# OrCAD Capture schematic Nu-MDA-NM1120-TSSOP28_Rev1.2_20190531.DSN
size A4; title: NM1120_MDA; rev: V1.2
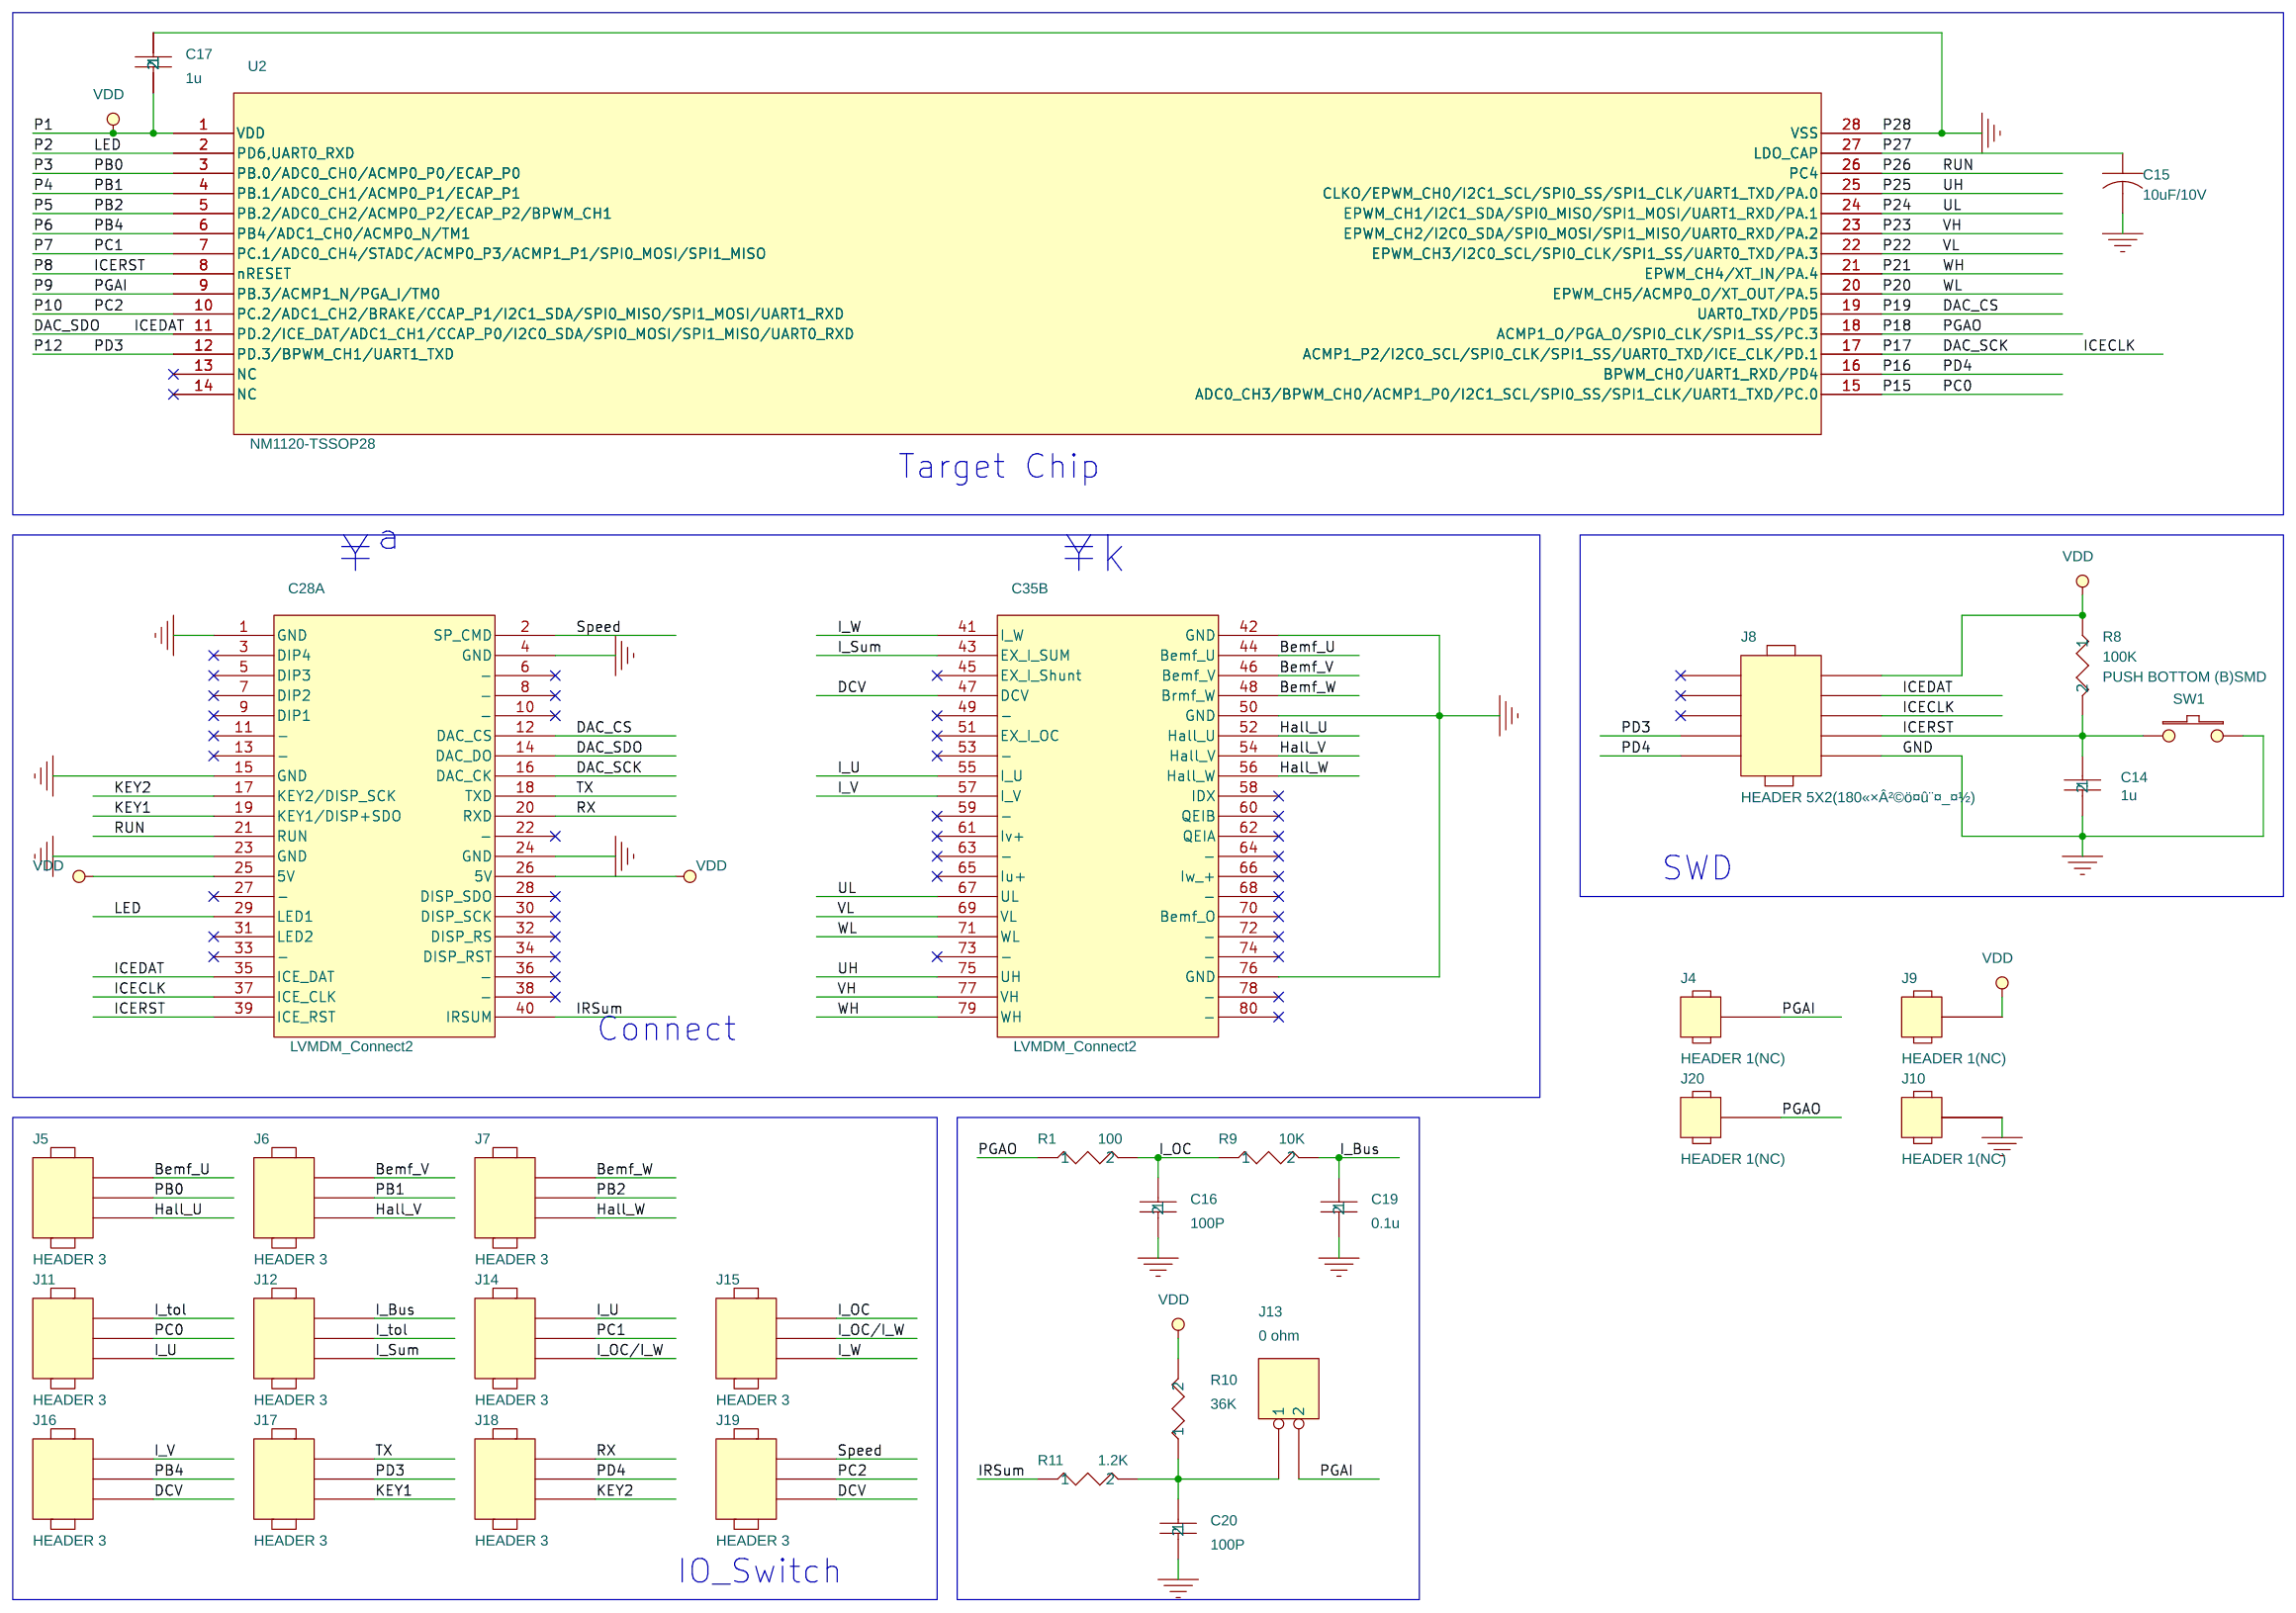
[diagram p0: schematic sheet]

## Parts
C14  1u  [C0603]
C15  10uF/10V  [TANT-A]
C16  100P  [C0603]
C17  1u  [C0603]
C19  0.1u  [C0603]
C20  100P  [C0603]
C28  LVMDM_Connect2  [LVMDM_Connect]  (section A)
C35  LVMDM_Connect2  [LVMDM_Connect]  (section B)
J4  HEADER 1(NC)  [sip-1p]
J5  HEADER 3  [HEADER3]
J6  HEADER 3  [HEADER3]
J7  HEADER 3  [HEADER3]
J8  HEADER 5X2(180«×Â²©ö¤û¨¤_¤½)  [header2x5]
J9  HEADER 1(NC)  [sip-1p]
J10  HEADER 1(NC)  [sip-1p]
J11  HEADER 3  [HEADER3]
J12  HEADER 3  [HEADER3]
J13  0 ohm  [SIP-2P]
J14  HEADER 3  [HEADER3]
J15  HEADER 3  [HEADER3]
J16  HEADER 3  [HEADER3]
J17  HEADER 3  [HEADER3]
J18  HEADER 3  [HEADER3]
J19  HEADER 3  [HEADER3]
J20  HEADER 1(NC)  [sip-1p]
R1  100  [R0603]
R8  100K  [R0603]
R9  10K  [R0603]
R10  36K  [R0603]
R11  1.2K  [R0603]
SW1  PUSH BOTTOM (B)SMD  [SW_SMD_HSM]
U2  NM1120-TSSOP28  [TSSOP28_1]

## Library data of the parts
C14 = C_1u
C15 = C_1uF_16V
C16 = C_0.1u_1
C17 = C_0.1u_3
C19 = C_0.1u
C20 = C_0.1u_2
C28 C35 = LVMDM_Connect2
J4 J9 J10 J20 = HEADER_1
J5-J7 J11 J12 J14-J19 = HEADER_3
J8 = HEADER_5X2
J13 = Header_0_ohm
R1 = R_10K_1
R8 = R_100K
R9 = R_10K
R10 = R_10K_3
R11 = R_10K_2
SW1 = PUSH_BOTTOM_(B)
U2 = NM1120_2

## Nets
GND: C14.2 C15.2 C16.2 C17.1 C19.2 C20.2 C28.1(GND) C28.4(GND) C28.15(GND) C28.23(GND) C28.24(GND) C35.42(GND) C35.50(GND) C35.76(GND) J8.10 J10.1 SW1.2 U2.28(VSS)
VDD: C17.2 C28.25(5V) C28.26(5V) J8.2 J9.1 R8.1 R10.2 U2.1(VDD)
Bemf_U: C35.44(Bemf_U) J5.1
Bemf_V: C35.46(Bemf_V) J6.1
Bemf_W: C35.48(Brmf_W) J7.1
DAC_CS: C28.12(DAC_CS) U2.19(UART0_TXD/PD5)
DAC_SDO: C28.14(DAC_DO) C28.35(ICE_DAT) J8.4 U2.11(PD.2/ICE_DAT/ADC1_CH1/CCAP_P0/I2C0_SDA/SPI0_MOSI/SPI1_MISO/UART0_RXD)
DCV: C35.47(DCV) J16.3 J19.3
Hall_U: C35.52(Hall_U) J5.3
Hall_V: C35.54(Hall_V) J6.3
Hall_W: C35.56(Hall_W) J7.3
I_Bus: C19.1 J12.1 R9.2
I_OC: C16.1 J15.1 R1.2 R9.1
I_OC/I_W: J14.3 J15.2
I_Sum: C35.43(EX_I_SUM) J12.3
I_tol: J11.1 J12.2
I_U: C35.55(I_U) J11.3 J14.1
I_V: C35.57(I_V) J16.1
I_W: C35.41(I_W) J15.3
ICECLK: C28.16(DAC_CK) C28.37(ICE_CLK) J8.6 U2.17(ACMP1_P2/I2C0_SCL/SPI0_CLK/SPI1_SS/UART0_TXD/ICE_CLK/PD.1)
ICERST: C14.1 C28.39(ICE_RST) J8.8 R8.2 SW1.1 U2.8(nRESET)
IRSum: C28.40(IRSUM) R11.1
KEY1: C28.19(KEY1/DISP+SDO) J17.3
KEY2: C28.17(KEY2/DISP_SCK) J18.3
LED: C28.29(LED1) U2.2(PD6,UART0_RXD)
P3: J5.2 U2.3(PB.0/ADC0_CH0/ACMP0_P0/ECAP_P0)
P4: J6.2 U2.4(PB.1/ADC0_CH1/ACMP0_P1/ECAP_P1)
P5: J7.2 U2.5(PB.2/ADC0_CH2/ACMP0_P2/ECAP_P2/BPWM_CH1)
P6: J16.2 U2.6(PB4/ADC1_CH0/ACMP0_N/TM1)
P7: J14.2 U2.7(PC.1/ADC0_CH4/STADC/ACMP0_P3/ACMP1_P1/SPI0_MOSI/SPI1_MISO)
P9: J4.1 J13.2 U2.9(PB.3/ACMP1_N/PGA_I/TM0)
P10: J19.2 U2.10(PC.2/ADC1_CH2/BRAKE/CCAP_P1/I2C1_SDA/SPI0_MISO/SPI1_MOSI/UART1_RXD)
P12: J8.7 J17.2 U2.12(PD.3/BPWM_CH1/UART1_TXD)
P15: J11.2 U2.15(ADC0_CH3/BPWM_CH0/ACMP1_P0/I2C1_SCL/SPI0_SS/SPI1_CLK/UART1_TXD/PC.0)
P16: J8.9 J18.2 U2.16(BPWM_CH0/UART1_RXD/PD4)
P18: J20.1 R1.1 U2.18(ACMP1_O/PGA_O/SPI0_CLK/SPI1_SS/PC.3)
P20: C35.71(WL) U2.20(EPWM_CH5/ACMP0_O/XT_OUT/PA.5)
P21: C35.79(WH) U2.21(EPWM_CH4/XT_IN/PA.4)
P22: C35.69(VL) U2.22(EPWM_CH3/I2C0_SCL/SPI0_CLK/SPI1_SS/UART0_TXD/PA.3)
P23: C35.77(VH) U2.23(EPWM_CH2/I2C0_SDA/SPI0_MOSI/SPI1_MISO/UART0_RXD/PA.2)
P24: C35.67(UL) U2.24(EPWM_CH1/I2C1_SDA/SPI0_MISO/SPI1_MOSI/UART1_RXD/PA.1)
P25: C35.75(UH) U2.25(CLKO/EPWM_CH0/I2C1_SCL/SPI0_SS/SPI1_CLK/UART1_TXD/PA.0)
P26: C28.21(RUN) U2.26(PC4)
P27: C15.1 U2.27(LDO_CAP)
RX: C28.20(RXD) J18.1
Speed: C28.2(SP_CMD) J19.1
TX: C28.18(TXD) J17.1
N18198: C20.1 J13.1 R10.1 R11.2

Not connected (* = marked no-connect by the designer): C28 3(DIP4)* 5(DIP3)* 6(-)* 7(DIP2)* 8(-)* 9(DIP1)* 10(-)* 11(-)* 13(-)* 22(-)* 27(-)* 28(DISP_SDO)* 30(DISP_SCK)* 31(LED2)* 32(DISP_RS)* 33(-)* 34(DISP_RST)* 36(-)* 38(-)*; C35 45(EX_I_Shunt)* 49(-)* 51(EX_I_OC)* 53(-)* 58(IDX)* 59(-)* 60(QEIB)* 61(Iv+)* 62(QEIA)* 63(-)* 64(-)* 65(Iu+)* 66(Iw_+)* 68(-)* 70(Bemf_O)* 72(-)* 73(-)* 74(-)* 78(-)* 80(-)*; J8 1* 3* 5*; U2 13(NC)* 14(NC)*

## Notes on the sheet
- Target Chip
- ¥ª
- ¥k
- SWD
- Connect
- IO_Switch
